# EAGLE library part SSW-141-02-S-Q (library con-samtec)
THROUGH-HOLE .025" SQ POST SOCKET Source: Samtec SSW.pdf
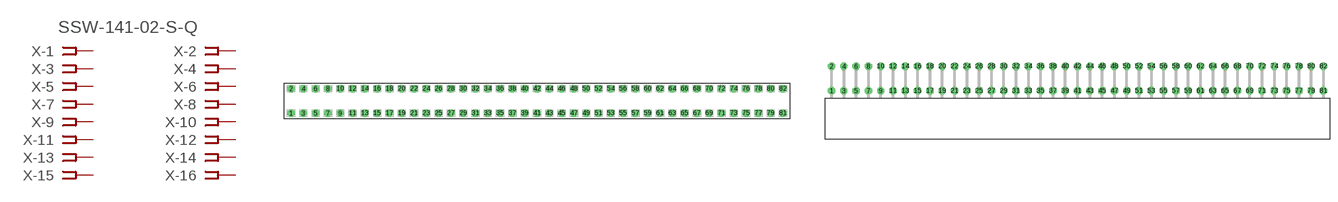
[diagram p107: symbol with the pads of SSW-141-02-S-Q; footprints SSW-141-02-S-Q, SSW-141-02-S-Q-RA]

Designator prefix X; gates -1=FPINV -2=FPIN -3=FPIN -4=FPIN -5=FPIN -6=FPIN -7=FPIN -8=FPIN -9=FPIN -10=FPIN -11=FPIN -12=FPIN -13=FPIN -14=FPIN -15=FPIN -16=FPIN -17=FPIN -18=FPIN -19=FPIN -20=FPIN -21=FPIN -22=FPIN -23=FPIN -24=FPIN -25=FPIN -26=FPIN -27=FPIN -28=FPIN -29=FPIN -30=FPIN -31=FPIN -32=FPIN -33=FPIN -34=FPIN -35=FPIN -36=FPIN -37=FPIN -38=FPIN -39=FPIN -40=FPIN -41=FPIN -42=FPIN -43=FPIN -44=FPIN -45=FPIN -46=FPIN -47=FPIN -48=FPIN -49=FPIN -50=FPIN -51=FPIN -52=FPIN -53=FPIN -54=FPIN -55=FPIN -56=FPIN -57=FPIN -58=FPIN -59=FPIN -60=FPIN -61=FPIN -62=FPIN -63=FPIN -64=FPIN -65=FPIN -66=FPIN -67=FPIN -68=FPIN -69=FPIN -70=FPIN -71=FPIN -72=FPIN -73=FPIN -74=FPIN -75=FPIN -76=FPIN -77=FPIN -78=FPIN -79=FPIN -80=FPIN -81=FPIN -82=FPIN

## SSW-141-02-S-Q (OC_FARNELL: unknown; OC_NEWARK: unknown)  [SSW-141-02-S-Q]
1  -1:1  pas
2  -2:1  pas
3  -3:1  pas
4  -4:1  pas
5  -5:1  pas
6  -6:1  pas
7  -7:1  pas
8  -8:1  pas
9  -9:1  pas
10  -10:1  pas
11  -11:1  pas
12  -12:1  pas
13  -13:1  pas
14  -14:1  pas
15  -15:1  pas
16  -16:1  pas
17  -17:1  pas
18  -18:1  pas
19  -19:1  pas
20  -20:1  pas
21  -21:1  pas
22  -22:1  pas
23  -23:1  pas
24  -24:1  pas
25  -25:1  pas
26  -26:1  pas
27  -27:1  pas
28  -28:1  pas
29  -29:1  pas
30  -30:1  pas
31  -31:1  pas
32  -32:1  pas
33  -33:1  pas
34  -34:1  pas
35  -35:1  pas
36  -36:1  pas
37  -37:1  pas
38  -38:1  pas
39  -39:1  pas
40  -40:1  pas
41  -41:1  pas
42  -42:1  pas
43  -43:1  pas
44  -44:1  pas
45  -45:1  pas
46  -46:1  pas
47  -47:1  pas
48  -48:1  pas
49  -49:1  pas
50  -50:1  pas
51  -51:1  pas
52  -52:1  pas
53  -53:1  pas
54  -54:1  pas
55  -55:1  pas
56  -56:1  pas
57  -57:1  pas
58  -58:1  pas
59  -59:1  pas
60  -60:1  pas
61  -61:1  pas
62  -62:1  pas
63  -63:1  pas
64  -64:1  pas
65  -65:1  pas
66  -66:1  pas
67  -67:1  pas
68  -68:1  pas
69  -69:1  pas
70  -70:1  pas
71  -71:1  pas
72  -72:1  pas
73  -73:1  pas
74  -74:1  pas
75  -75:1  pas
76  -76:1  pas
77  -77:1  pas
78  -78:1  pas
79  -79:1  pas
80  -80:1  pas
81  -81:1  pas
82  -82:1  pas

## SSW-141-02-S-QRA (OC_FARNELL: unknown; OC_NEWARK: unknown)  [SSW-141-02-S-Q-RA]
Pads as for SSW-141-02-S-Q

## Footprint SSW-141-02-S-Q (pad centres in mm)
THROUGH-HOLE .025" SQ POST SOCKET Source: Samtec SSW.pdf
drill 1 pad 1.5 octagon: 1 -50.8,-2.54; 2 -50.8,2.54; 3 -48.26,-2.54; 4 -48.26,2.54; 5 -45.72,-2.54; 6 -45.72,2.54; 7 -43.18,-2.54; 8 -43.18,2.54; 9 -40.64,-2.54; 10 -40.64,2.54; 11 -38.1,-2.54; 12 -38.1,2.54; 13 -35.56,-2.54; 14 -35.56,2.54; 15 -33.02,-2.54; 16 -33.02,2.54; 17 -30.48,-2.54; 18 -30.48,2.54; 19 -27.94,-2.54; 20 -27.94,2.54; 21 -25.4,-2.54; 22 -25.4,2.54; 23 -22.86,-2.54; 24 -22.86,2.54; 25 -20.32,-2.54; 26 -20.32,2.54; 27 -17.78,-2.54; 28 -17.78,2.54; 29 -15.24,-2.54; 30 -15.24,2.54; 31 -12.7,-2.54; 32 -12.7,2.54; 33 -10.16,-2.54; 34 -10.16,2.54; 35 -7.62,-2.54; 36 -7.62,2.54; 37 -5.08,-2.54; 38 -5.08,2.54; 39 -2.54,-2.54; 40 -2.54,2.54; 41 0,-2.54; 42 0,2.54; 43 2.54,-2.54; 44 2.54,2.54; 45 5.08,-2.54; 46 5.08,2.54; 47 7.62,-2.54; 48 7.62,2.54; 49 10.16,-2.54; 50 10.16,2.54; 51 12.7,-2.54; 52 12.7,2.54; 53 15.24,-2.54; 54 15.24,2.54; 55 17.78,-2.54; 56 17.78,2.54; 57 20.32,-2.54; 58 20.32,2.54; 59 22.86,-2.54; 60 22.86,2.54; 61 25.4,-2.54; 62 25.4,2.54; 63 27.94,-2.54; 64 27.94,2.54; 65 30.48,-2.54; 66 30.48,2.54; 67 33.02,-2.54; 68 33.02,2.54; 69 35.56,-2.54; 70 35.56,2.54; 71 38.1,-2.54; 72 38.1,2.54; 73 40.64,-2.54; 74 40.64,2.54; 75 43.18,-2.54; 76 43.18,2.54; 77 45.72,-2.54; 78 45.72,2.54; 79 48.26,-2.54; 80 48.26,2.54; 81 50.8,-2.54; 82 50.8,2.54

## Footprint SSW-141-02-S-Q-RA (pad centres in mm)
THROUGH-HOLE .025" SQ POST SOCKET Source: Samtec SSW.pdf
drill 1 pad 1.5 octagon: 1 -50.8,1.524; 2 -50.8,6.604; 3 -48.26,1.524; 4 -48.26,6.604; 5 -45.72,1.524; 6 -45.72,6.604; 7 -43.18,1.524; 8 -43.18,6.604; 9 -40.64,1.524; 10 -40.64,6.604; 11 -38.1,1.524; 12 -38.1,6.604; 13 -35.56,1.524; 14 -35.56,6.604; 15 -33.02,1.524; 16 -33.02,6.604; 17 -30.48,1.524; 18 -30.48,6.604; 19 -27.94,1.524; 20 -27.94,6.604; 21 -25.4,1.524; 22 -25.4,6.604; 23 -22.86,1.524; 24 -22.86,6.604; 25 -20.32,1.524; 26 -20.32,6.604; 27 -17.78,1.524; 28 -17.78,6.604; 29 -15.24,1.524; 30 -15.24,6.604; 31 -12.7,1.524; 32 -12.7,6.604; 33 -10.16,1.524; 34 -10.16,6.604; 35 -7.62,1.524; 36 -7.62,6.604; 37 -5.08,1.524; 38 -5.08,6.604; 39 -2.54,1.524; 40 -2.54,6.604; 41 0,1.524; 42 0,6.604; 43 2.54,1.524; 44 2.54,6.604; 45 5.08,1.524; 46 5.08,6.604; 47 7.62,1.524; 48 7.62,6.604; 49 10.16,1.524; 50 10.16,6.604; 51 12.7,1.524; 52 12.7,6.604; 53 15.24,1.524; 54 15.24,6.604; 55 17.78,1.524; 56 17.78,6.604; 57 20.32,1.524; 58 20.32,6.604; 59 22.86,1.524; 60 22.86,6.604; 61 25.4,1.524; 62 25.4,6.604; 63 27.94,1.524; 64 27.94,6.604; 65 30.48,1.524; 66 30.48,6.604; 67 33.02,1.524; 68 33.02,6.604; 69 35.56,1.524; 70 35.56,6.604; 71 38.1,1.524; 72 38.1,6.604; 73 40.64,1.524; 74 40.64,6.604; 75 43.18,1.524; 76 43.18,6.604; 77 45.72,1.524; 78 45.72,6.604; 79 48.26,1.524; 80 48.26,6.604; 81 50.8,1.524; 82 50.8,6.604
